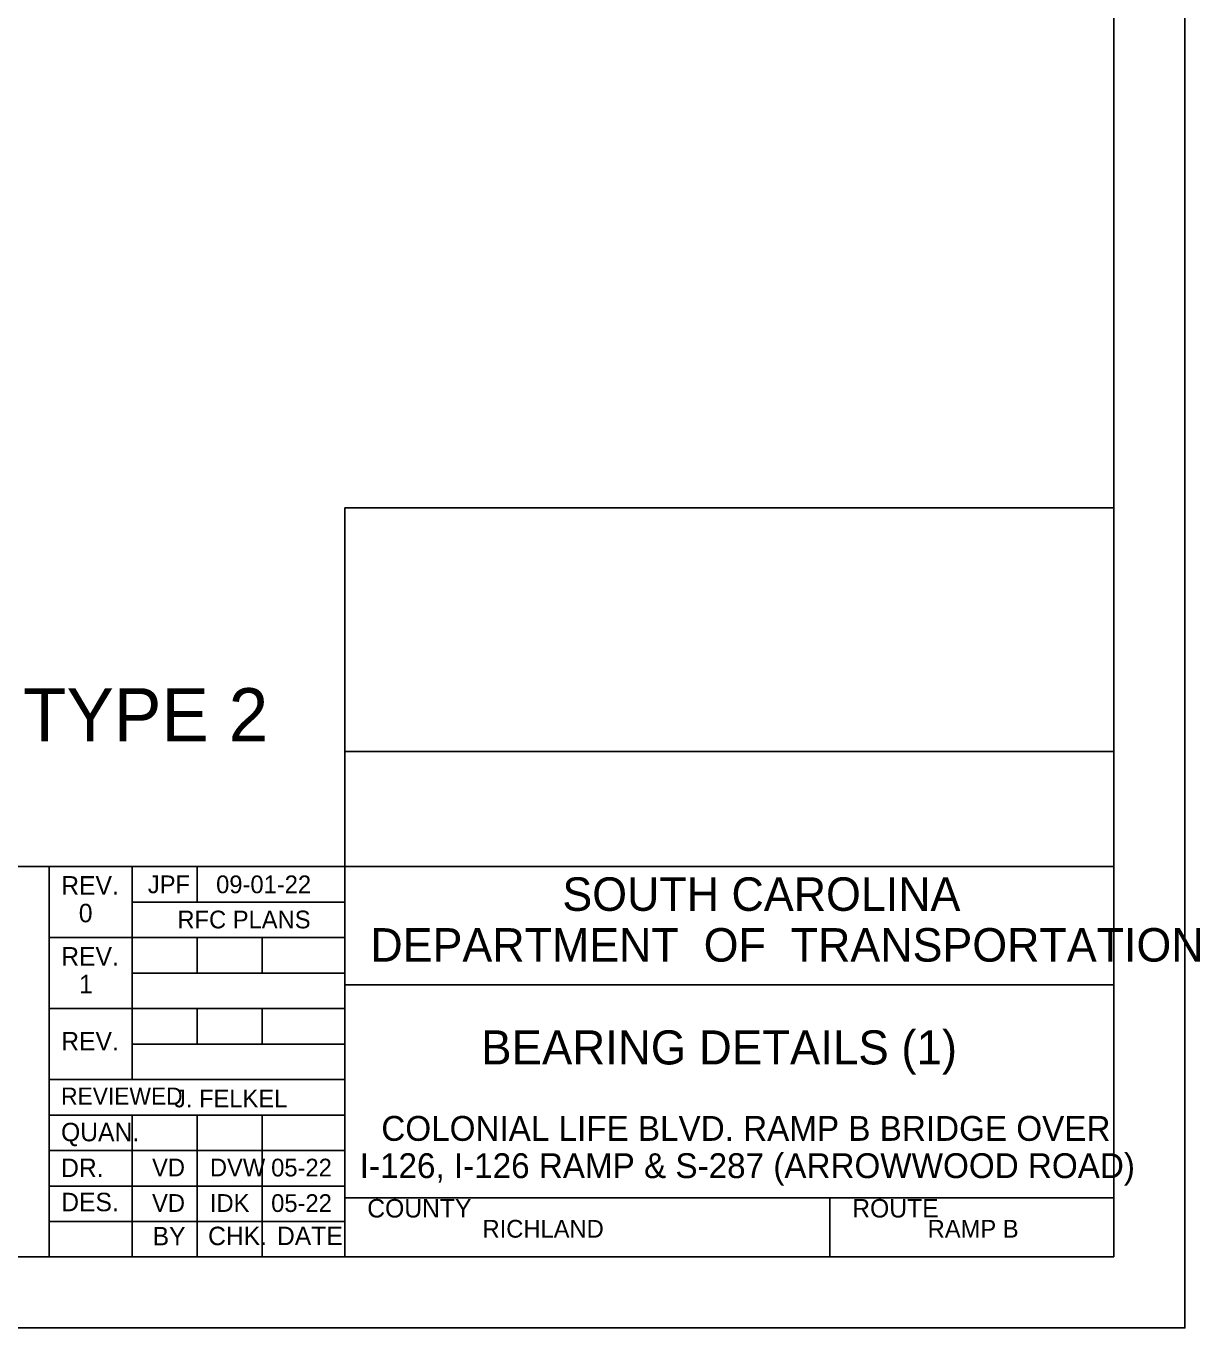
# Model space of a CAD drawing. Extents: x -125.5 to -89.4, y -5.1 to 16.9.
# Drawn here: x -97.7 to -89.43, y -5.07 to 4.11 of the extents above; entities that cross this region are included whole.
import ezdxf

# ---------------------------------------------------------------- set-up
doc = ezdxf.new("R2010")
doc.units = 0
for name, color, linetype in [('BR_BORDER LINES', 7, 'Continuous'), ('BR_TEXT', 7, 'Continuous'), ('Level 31', 7, 'Continuous')]:
    doc.layers.add(name, color=color, linetype=linetype)

msp = doc.modelspace()

# ---------------------------------------------------------------- linework, layer by layer
at = {"layer": 'BR_BORDER LINES'}
for p, q in [((-90.0334, -4.5662), (-90.0334, 16.4338)), ((-95.4503, -4.5662), (-95.4503, 0.7104)), ((-95.4503, 0.7104), (-90.0334, 0.7104)), ((-95.4501, -1.0044), (-90.0334, -1.0044)), ((-102.8989, -1.8161), (-97.5337, -1.8161)), ((-97.5337, -4.5662), (-97.5337, -1.8161)), ((-97.5337, -1.8161), (-90.0334, -1.8161)), ((-96.9503, -1.8161), (-96.9503, -3.3161)), ((-96.492, -2.0661), (-96.492, -1.8161)), ((-96.9503, -2.0661), (-95.4503, -2.0661)), ((-97.5337, -2.3161), (-95.4503, -2.3161)), ((-96.492, -2.5661), (-96.492, -2.3161)), ((-96.0336, -2.5661), (-96.0336, -2.3161)), ((-96.9503, -2.5661), (-95.4503, -2.5661)), ((-95.4503, -2.6494), (-95.4503, -2.6494)), ((-95.4503, -2.6495), (-90.0332, -2.6495)), ((-97.5337, -2.8161), (-95.4503, -2.8161)), ((-96.492, -3.0661), (-96.492, -2.8161)), ((-96.0336, -3.0661), (-96.0336, -2.8161)), ((-96.9503, -3.0661), (-95.4503, -3.0661)), ((-97.5337, -3.3161), (-95.4503, -3.3161)), ((-97.5337, -3.5661), (-95.4503, -3.5661)), ((-96.9503, -3.5661), (-96.9503, -4.5662)), ((-96.492, -3.5661), (-96.492, -4.5662)), ((-96.0336, -3.5661), (-96.0336, -4.5662)), ((-97.5337, -3.8161), (-95.4503, -3.8161)), ((-97.5337, -4.0662), (-95.4503, -4.0662)), ((-95.4503, -4.1495), (-90.0334, -4.1495)), ((-95.3527, -4.1495), (-90.0334, -4.1495)), ((-92.0335, -4.5662), (-92.0335, -4.1495)), ((-97.5337, -4.3162), (-95.4503, -4.3162)), ((-123.6994, -4.5662), (-90.0334, -4.5662))]:
    msp.add_line(p, q, dxfattribs=at)
at = {"layer": 'Level 31'}
msp.add_line((-92.7416, -3.0897), (-92.7416, -3.0897), dxfattribs=at)
msp.add_lwpolyline([(-125.5328, -5.0661), (-89.5328, -5.0661), (-89.5328, 16.9339), (-125.5328, 16.9339)], close=True, dxfattribs=at)

# ---------------------------------------------------------------- texts
at = {"layer": 'BR_TEXT'}
for s, height, p in [('BEARING PAD DETAILS - TYPE 2', 0.375, (-103.821, -0.9342)), ('REV.', 0.13001, (-97.449, -2.0132)), ('JPF', 0.12499, (-96.8388, -2.0036)), ('09-01-22', 0.12499, (-96.3576, -2.0036)), ('SOUTH CAROLINA', 0.23587, (-93.9184, -2.1277)), ('0', 0.13, (-97.3251, -2.2082)), ('RFC PLANS', 0.12499, (-96.6304, -2.2512)), ('DEPARTMENT  OF  TRANSPORTATION', 0.23587, (-95.2711, -2.4854)), ('REV.', 0.13001, (-97.449, -2.5132)), ('1', 0.13, (-97.3231, -2.7082)), ('REV.', 0.13001, (-97.449, -3.1107)), ('BEARING DETAILS (1)', 0.24, (-94.4904, -3.2097)), ('REVIEWED', 0.12, (-97.4497, -3.4926)), ('J. FELKEL', 0.12499, (-96.6547, -3.5118)), ('COLONIAL LIFE BLVD. RAMP B BRIDGE OVER', 0.175, (-95.1938, -3.7479)), ('QUAN.', 0.13001, (-97.4503, -3.751)), ('I-126, I-126 RAMP & S-287 (ARROWWOOD ROAD) ', 0.175, (-95.3459, -4.0104)), ('DR.', 0.13001, (-97.4501, -4.0025)), ('VD', 0.12499, (-96.8091, -3.9979)), ('DVW', 0.12499, (-96.4015, -3.9979)), ('05-22', 0.12499, (-95.9699, -3.9989)), ('DES.', 0.13001, (-97.449, -4.2438)), ('VD', 0.12499, (-96.8091, -4.2484)), ('IDK', 0.12499, (-96.4015, -4.2484)), ('05-22', 0.12499, (-95.9699, -4.2489)), ('COUNTY', 0.13001, (-95.293, -4.2879)), ('ROUTE', 0.13001, (-91.8762, -4.2879)), ('RICHLAND', 0.12499, (-94.4809, -4.4299)), ('RAMP B', 0.12499, (-91.3448, -4.4299)), ('BY', 0.13001, (-96.805, -4.4842)), ('CHK.', 0.13001, (-96.4142, -4.4828)), ('DATE', 0.13001, (-95.929, -4.4827))]:
    msp.add_text(s, height=height, dxfattribs=at).set_placement(p)

doc.saveas('drawing.dxf')
